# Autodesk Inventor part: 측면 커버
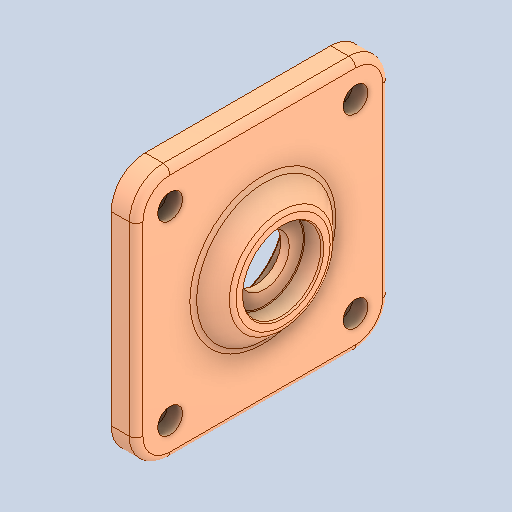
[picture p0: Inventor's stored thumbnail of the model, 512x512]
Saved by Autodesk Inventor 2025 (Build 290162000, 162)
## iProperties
Created: 2026-01
Part Number: 측면 커버
Material: 알루미늄 6061
Document SubType Name: Modeling
Designer: KDI
Density: 2.7 g/cm^3
Appearance: 기본값
Author: jhkim
Sending System: Autodesk Inventor 2026
Preprocessor: ST-DEVELOPER v20.1
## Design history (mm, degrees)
feature "솔리드1"
node "솔리드2"
